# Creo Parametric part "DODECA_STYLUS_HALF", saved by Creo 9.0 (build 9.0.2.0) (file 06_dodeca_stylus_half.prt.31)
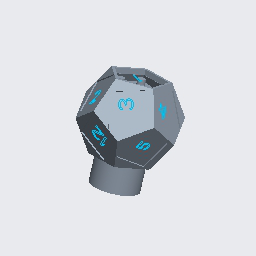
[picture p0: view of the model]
Units: millimeter Kilogram Sec (mmKs); MM, KILOGRAM, SECS

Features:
  1. coordinate system
  2. datum plane "RIGHT"
  3. datum plane "TOP"
  4. datum plane "FRONT"
  5. protrusion
  6. cut
  7. cut
  8. curve
  9. cut
  10. datum axis
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
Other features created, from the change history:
  extruded cut "Extrude 36" (3 times)
  extruded cut "Extrude 37"
  extruded cut "Extrude 38"

Other named items: FACE1, FACE2, FACE3, FACE4, FACE5, FACE6, FACE11, FACE12, FACE10, FACE8, FACE7, DEFAULT_1, DEFAULT_2, DEFAULT_3, DEFAULT_4, DEFAULT_5, DEFAULT_6, DEFAULT_7, DEFAULT_8, DEFAULT_9, DEFAULT_10, DEFAULT_11, DEFAULT_12, DEFAULT_13, DEFAULT_14, DEFAULT_15, DEFAULT_16, DEFAULT_17, DEFAULT_18, DEFAULT_19, DEFAULT_20, DEFAULT_21, DEFAULT_22, DEFAULT_23, DEFAULT_24

Surfaces: 115 plane, 10 cylinder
